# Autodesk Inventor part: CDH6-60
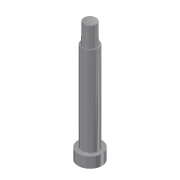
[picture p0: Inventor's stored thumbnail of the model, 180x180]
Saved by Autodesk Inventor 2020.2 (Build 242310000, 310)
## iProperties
Created: 2015-01
Part Number: CDH6-60
Material: Ogólny
Description: Straight Core Pin
Document SubType Name: Modeling
Designer: F.Stasiak
Density: 1 g/cm^3
Appearance: Domyślna
Catalog Web Link: www.expertbooks.pl
Manager: www.cadconsulting.pl
Company: Fabian Stasiak CAD Consulting
Author: F.Stasiak
Subject: Zbiór ćwiczeń. Autodesk Inventor 2020. Kurs Professional
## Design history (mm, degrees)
node "Forma_ZEGAR_260_ZEGAR_260_Rdzeń formujący7_Base"
feature "Solid1::Forma_ZEGAR_260_ZEGAR_260_Rdzeń formujący7_Base"
tag "Bryła wyprowadzona1"
node "Bryła1"
feature "Forma_ZEGAR_260_ZEGAR_260_Rdzeń formujący7_Base_Bodies"
